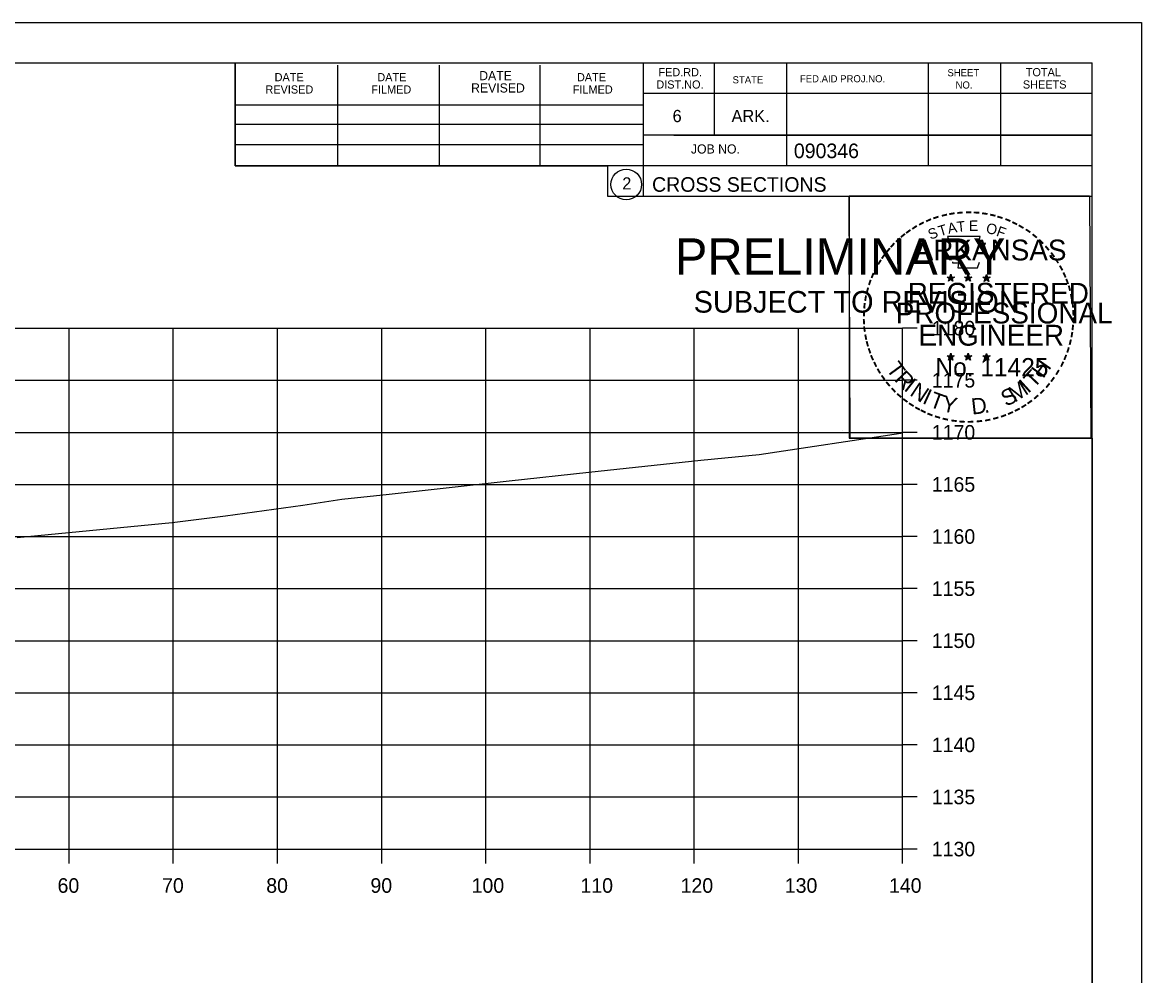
# Model space of a CAD drawing. Extents: x 1368971 to 1374497, y 378717 to 381839.
# Drawn here: x 1369609.3 to 1369716.8, y 380922.1 to 381013.6 of the extents above; entities that cross this region are included whole.
import ezdxf

# ---------------------------------------------------------------- set-up
doc = ezdxf.new("R2010")
doc.units = 0
for name, color, linetype in [('R_Axis', 7, 'Continuous'), ('R_Axis Annot', 7, 'Continuous'), ('R_Border', 7, 'Continuous'), ('R_Border PE', 7, 'Continuous'), ('R_Border Prem', 7, 'Continuous'), ('R_Exist Surface', 7, 'Continuous'), ('R_Grid', 7, 'Continuous'), ('R_No Plot', 7, 'Continuous')]:
    doc.layers.add(name, color=color, linetype=linetype)

msp = doc.modelspace()

# ---------------------------------------------------------------- linework, layer by layer
at = {"layer": 'R_Axis'}
for p, q in [((1369693.83, 380934.26), (1369693.83, 380984.26)), ((1369695.23, 380984.26), (1369693.83, 380984.26)), ((1369695.23, 380979.26), (1369693.83, 380979.26)), ((1369695.23, 380974.26), (1369693.83, 380974.26)), ((1369695.23, 380969.26), (1369693.83, 380969.26)), ((1369695.23, 380964.26), (1369693.83, 380964.26)), ((1369695.23, 380959.26), (1369693.83, 380959.26)), ((1369695.23, 380954.26), (1369693.83, 380954.26)), ((1369695.23, 380949.26), (1369693.83, 380949.26)), ((1369695.23, 380944.26), (1369693.83, 380944.26)), ((1369695.23, 380939.26), (1369693.83, 380939.26)), ((1369413.83, 380934.26), (1369693.83, 380934.26)), ((1369613.83, 380932.86), (1369613.83, 380934.26)), ((1369623.83, 380932.86), (1369623.83, 380934.26)), ((1369633.83, 380932.86), (1369633.83, 380934.26)), ((1369643.83, 380932.86), (1369643.83, 380934.26)), ((1369653.83, 380932.86), (1369653.83, 380934.26)), ((1369663.83, 380932.86), (1369663.83, 380934.26)), ((1369673.83, 380932.86), (1369673.83, 380934.26)), ((1369683.83, 380932.86), (1369683.83, 380934.26)), ((1369693.83, 380932.86), (1369693.83, 380934.26)), ((1369695.23, 380934.26), (1369693.83, 380934.26))]:
    msp.add_line(p, q, dxfattribs=at)
at = {"layer": 'R_Border'}
for p, q in [((1369395.83, 381009.72), (1369712.01, 381009.72)), ((1369629.75, 380999.84), (1369629.75, 381009.72)), ((1369668.91, 381009.72), (1369668.91, 380996.92)), ((1369675.75, 381009.72), (1369675.75, 381002.78)), ((1369682.69, 381009.72), (1369682.69, 380999.84)), ((1369696.27, 381009.72), (1369696.27, 380999.84)), ((1369703.21, 381009.72), (1369703.21, 380999.84)), ((1369712.01, 380804.26), (1369712.01, 381009.72)), ((1369639.61, 380999.84), (1369639.61, 381009.52)), ((1369649.37, 380999.84), (1369649.37, 381009.52)), ((1369659.05, 380999.84), (1369659.05, 381009.52)), ((1369712.01, 381006.78), (1369668.91, 381006.78)), ((1369712.01, 381006.8), (1369712.01, 381006.8)), ((1369629.75, 381005.7), (1369668.91, 381005.7)), ((1369629.75, 381003.84), (1369668.91, 381003.84)), ((1369712.01, 381002.78), (1369668.91, 381002.78)), ((1369671.87, 381002.78), (1369712.01, 381002.78)), ((1369629.75, 380999.84), (1369629.75, 381001.9)), ((1369629.75, 381001.9), (1369668.91, 381001.9)), ((1369712.01, 380999.84), (1369629.75, 380999.84)), ((1369668.91, 380996.92), (1369712.01, 380996.92))]:
    msp.add_line(p, q, dxfattribs=at)
msp.add_circle((1369667.3, 380998.05), 1.47, dxfattribs=at)
at = {"layer": 'R_Border PE'}
for p, q in [((1369698.1, 380989.17), (1369698.45, 380989.06)), ((1369698.1, 380989.17), (1369698.35, 380989.13)), ((1369698.1, 380989.17), (1369698.34, 380989.05)), ((1369698.45, 380989.43), (1369698.41, 380989.17)), ((1369698.45, 380989.06), (1369698.45, 380989.43)), ((1369698.45, 380989.43), (1369698.5, 380989.18)), ((1369698.8, 380989.17), (1369698.45, 380989.06)), ((1369698.8, 380989.17), (1369698.51, 380989.12)), ((1369698.8, 380989.17), (1369698.59, 380989.07)), ((1369699.77, 380989.17), (1369700.12, 380989.06)), ((1369699.77, 380989.17), (1369700.02, 380989.13)), ((1369699.77, 380989.17), (1369700.01, 380989.05)), ((1369700.12, 380989.43), (1369700.08, 380989.17)), ((1369700.12, 380989.06), (1369700.12, 380989.43)), ((1369700.12, 380989.43), (1369700.17, 380989.18)), ((1369700.47, 380989.17), (1369700.12, 380989.06)), ((1369700.47, 380989.17), (1369700.18, 380989.12)), ((1369700.47, 380989.17), (1369700.26, 380989.07)), ((1369701.53, 380989.16), (1369701.88, 380989.05)), ((1369701.53, 380989.16), (1369701.79, 380989.11)), ((1369701.53, 380989.16), (1369701.77, 380989.04)), ((1369701.88, 380989.41), (1369701.84, 380989.16)), ((1369701.88, 380989.05), (1369701.88, 380989.41)), ((1369701.88, 380989.41), (1369701.93, 380989.16)), ((1369702.23, 380989.16), (1369701.88, 380989.05)), ((1369702.23, 380989.16), (1369701.94, 380989.11)), ((1369702.23, 380989.16), (1369702.03, 380989.06)), ((1369698.23, 380988.76), (1369698.45, 380989.06)), ((1369698.23, 380988.76), (1369698.36, 380989.01)), ((1369698.23, 380988.76), (1369698.45, 380988.98)), ((1369698.66, 380988.76), (1369698.45, 380989.06)), ((1369698.66, 380988.76), (1369698.45, 380988.98)), ((1369698.66, 380988.76), (1369698.52, 380989.05)), ((1369699.9, 380988.76), (1369700.12, 380989.06)), ((1369699.9, 380988.76), (1369700.03, 380989.01)), ((1369699.9, 380988.76), (1369700.12, 380988.98)), ((1369700.33, 380988.76), (1369700.12, 380989.06)), ((1369700.33, 380988.76), (1369700.12, 380988.98)), ((1369700.33, 380988.76), (1369700.19, 380989.05)), ((1369701.67, 380988.75), (1369701.88, 380989.05)), ((1369701.67, 380988.75), (1369701.79, 380989)), ((1369701.67, 380988.75), (1369701.88, 380988.97)), ((1369702.1, 380988.75), (1369701.88, 380989.05)), ((1369702.1, 380988.75), (1369701.88, 380988.97)), ((1369702.1, 380988.75), (1369701.96, 380989.04)), ((1369698.44, 380981.85), (1369698.4, 380981.6)), ((1369698.44, 380981.49), (1369698.44, 380981.85)), ((1369698.44, 380981.85), (1369698.49, 380981.6)), ((1369700.11, 380981.85), (1369700.07, 380981.6)), ((1369700.11, 380981.49), (1369700.11, 380981.85)), ((1369700.11, 380981.85), (1369700.16, 380981.6)), ((1369701.88, 380981.84), (1369701.84, 380981.59)), ((1369701.88, 380981.48), (1369701.88, 380981.84)), ((1369701.88, 380981.84), (1369701.93, 380981.59)), ((1369698.1, 380981.6), (1369698.44, 380981.49)), ((1369698.1, 380981.6), (1369698.35, 380981.55)), ((1369698.1, 380981.6), (1369698.33, 380981.48)), ((1369698.23, 380981.19), (1369698.44, 380981.49)), ((1369698.23, 380981.19), (1369698.35, 380981.43)), ((1369698.23, 380981.19), (1369698.44, 380981.41)), ((1369698.79, 380981.6), (1369698.44, 380981.49)), ((1369698.66, 380981.19), (1369698.44, 380981.49)), ((1369698.66, 380981.19), (1369698.44, 380981.4)), ((1369698.79, 380981.6), (1369698.51, 380981.55)), ((1369698.66, 380981.19), (1369698.52, 380981.48)), ((1369698.79, 380981.6), (1369698.59, 380981.5)), ((1369699.76, 380981.6), (1369700.11, 380981.49)), ((1369699.76, 380981.6), (1369700.02, 380981.55)), ((1369699.76, 380981.6), (1369700, 380981.48)), ((1369699.9, 380981.19), (1369700.11, 380981.49)), ((1369699.9, 380981.19), (1369700.02, 380981.43)), ((1369699.9, 380981.19), (1369700.11, 380981.41)), ((1369700.46, 380981.6), (1369700.11, 380981.49)), ((1369700.33, 380981.19), (1369700.11, 380981.49)), ((1369700.33, 380981.19), (1369700.11, 380981.4)), ((1369700.46, 380981.6), (1369700.17, 380981.55)), ((1369700.33, 380981.19), (1369700.19, 380981.48)), ((1369700.46, 380981.6), (1369700.26, 380981.5)), ((1369701.53, 380981.59), (1369701.88, 380981.48)), ((1369701.53, 380981.59), (1369701.78, 380981.54)), ((1369701.53, 380981.59), (1369701.77, 380981.47)), ((1369701.66, 380981.18), (1369701.88, 380981.48)), ((1369701.66, 380981.18), (1369701.79, 380981.42)), ((1369701.66, 380981.18), (1369701.88, 380981.4)), ((1369702.23, 380981.59), (1369701.88, 380981.48)), ((1369702.09, 380981.18), (1369701.88, 380981.48)), ((1369702.09, 380981.18), (1369701.88, 380981.39)), ((1369702.23, 380981.59), (1369701.94, 380981.54)), ((1369702.09, 380981.18), (1369701.96, 380981.47)), ((1369702.23, 380981.59), (1369702.02, 380981.49))]:
    msp.add_line(p, q, dxfattribs=at)
for points in [[(1369698.14, 380993.05), (1369698.41, 380992.22)], [(1369701.65, 380992.13), (1369701.79, 380992.41), (1369701.11, 380992.39), (1369701.26, 380993.05), (1369698.14, 380993.05)], [(1369698.63, 380990.63), (1369698.63, 380990.54), (1369699.2, 380990.52), (1369699.14, 380990.05), (1369701.01, 380990.05), (1369701.21, 380990.58)], [(1369698.45, 380989.43), (1369698.66, 380988.76), (1369698.1, 380989.17), (1369698.8, 380989.17), (1369698.23, 380988.76), (1369698.45, 380989.43)], [(1369700.12, 380989.43), (1369700.33, 380988.76), (1369699.77, 380989.17), (1369700.47, 380989.17), (1369699.9, 380988.76), (1369700.12, 380989.43)], [(1369701.88, 380989.41), (1369702.1, 380988.75), (1369701.53, 380989.16), (1369702.23, 380989.16), (1369701.67, 380988.75), (1369701.88, 380989.41)], [(1369698.44, 380981.85), (1369698.66, 380981.19), (1369698.1, 380981.6), (1369698.79, 380981.6), (1369698.23, 380981.19), (1369698.44, 380981.85)], [(1369700.11, 380981.85), (1369700.33, 380981.19), (1369699.76, 380981.6), (1369700.46, 380981.6), (1369699.9, 380981.19), (1369700.11, 380981.85)], [(1369701.88, 380981.84), (1369702.09, 380981.18), (1369701.53, 380981.59), (1369702.23, 380981.59), (1369701.66, 380981.18), (1369701.88, 380981.84)]]:
    msp.add_lwpolyline(points, dxfattribs=at)
for centre, radius in [((1369698.45, 380989.06), 0.172), ((1369698.45, 380989.06), 0.145), ((1369698.45, 380989.06), 0.116), ((1369698.45, 380989.06), 0.0991), ((1369698.45, 380989.06), 0.0747), ((1369700.12, 380989.06), 0.172), ((1369700.12, 380989.06), 0.145), ((1369700.12, 380989.06), 0.116), ((1369700.12, 380989.06), 0.0991), ((1369700.12, 380989.06), 0.0747), ((1369701.88, 380989.05), 0.172), ((1369701.88, 380989.05), 0.145), ((1369701.88, 380989.05), 0.116), ((1369701.88, 380989.05), 0.0991), ((1369698.45, 380989.06), 0.0495), ((1369698.45, 380989.06), 0.0296), ((1369700.12, 380989.06), 0.0495), ((1369700.12, 380989.06), 0.0296), ((1369701.88, 380989.05), 0.0747), ((1369701.88, 380989.05), 0.0495), ((1369701.88, 380989.05), 0.0296), ((1369698.44, 380981.49), 0.172), ((1369698.44, 380981.49), 0.145), ((1369700.11, 380981.49), 0.172), ((1369700.11, 380981.49), 0.145), ((1369701.88, 380981.48), 0.172), ((1369701.88, 380981.48), 0.145), ((1369698.44, 380981.49), 0.116), ((1369698.44, 380981.49), 0.0991), ((1369698.44, 380981.49), 0.0747), ((1369698.44, 380981.49), 0.0495), ((1369698.44, 380981.49), 0.0296), ((1369700.11, 380981.49), 0.116), ((1369700.11, 380981.49), 0.0991), ((1369700.11, 380981.49), 0.0747), ((1369700.11, 380981.49), 0.0495), ((1369700.11, 380981.49), 0.0296), ((1369701.88, 380981.48), 0.116), ((1369701.88, 380981.48), 0.0991), ((1369701.88, 380981.48), 0.0747), ((1369701.88, 380981.48), 0.0495), ((1369701.88, 380981.48), 0.0296)]:
    msp.add_circle(centre, radius, dxfattribs=at)
at = {"layer": 'R_Exist Surface'}
msp.add_lwpolyline([(1369608.84, 380964.18), (1369623.73, 380965.59), (1369628.85, 380966.23), (1369636.25, 380967.27), (1369640, 380967.85), (1369644.55, 380968.34), (1369656.06, 380969.61), (1369663.7, 380970.45), (1369674.46, 380971.59), (1369680.05, 380972.12), (1369693.66, 380974.19), (1369693.83, 380974.21)], dxfattribs=at)
at = {"layer": 'R_Grid'}
for p, q in [((1369413.83, 380984.26), (1369693.83, 380984.26)), ((1369613.83, 380934.26), (1369613.83, 380984.26)), ((1369623.83, 380934.26), (1369623.83, 380984.26)), ((1369633.83, 380934.26), (1369633.83, 380984.26)), ((1369643.83, 380934.26), (1369643.83, 380984.26)), ((1369653.83, 380934.26), (1369653.83, 380984.26)), ((1369663.83, 380934.26), (1369663.83, 380984.26)), ((1369673.83, 380934.26), (1369673.83, 380984.26)), ((1369683.83, 380934.26), (1369683.83, 380984.26)), ((1369693.83, 380934.26), (1369693.83, 380984.26)), ((1369413.83, 380979.26), (1369693.83, 380979.26)), ((1369413.83, 380974.26), (1369693.83, 380974.26)), ((1369413.83, 380969.26), (1369693.83, 380969.26)), ((1369413.83, 380964.26), (1369693.83, 380964.26)), ((1369413.83, 380959.26), (1369693.83, 380959.26)), ((1369413.83, 380954.26), (1369693.83, 380954.26)), ((1369413.83, 380949.26), (1369693.83, 380949.26)), ((1369413.83, 380944.26), (1369693.83, 380944.26)), ((1369413.83, 380939.26), (1369693.83, 380939.26)), ((1369413.83, 380934.26), (1369693.83, 380934.26))]:
    msp.add_line(p, q, dxfattribs=at)
at = {"layer": 'R_No Plot'}
for p, q in [((1369383.43, 381013.61), (1369716.77, 381013.61)), ((1369688.05, 380974.46), (1369688.05, 380974.46))]:
    msp.add_line(p, q, dxfattribs=at)
for points in [[(1369383.43, 381013.61), (1369716.77, 381013.61), (1369716.77, 380800.27), (1369383.43, 380800.27)], [(1369629.75, 381009.72), (1369629.75, 380999.84), (1369665.49, 380999.84), (1369665.49, 380996.92), (1369688.69, 380996.92), (1369688.69, 380973.7), (1369712.01, 380973.7), (1369712.01, 380804.26), (1369395.83, 380804.26), (1369395.83, 381009.72)], [(1369688.69, 380996.95), (1369711.78, 380996.95), (1369711.9, 380973.7), (1369688.8, 380973.7)]]:
    msp.add_lwpolyline(points, close=True, dxfattribs=at)

# ---------------------------------------------------------------- texts
at = {"layer": 'R_Axis Annot'}
for s, p in [('1180', (1369696.63, 380983.56)), ('1175', (1369696.63, 380978.56)), ('1170', (1369696.63, 380973.56)), ('1165', (1369696.63, 380968.56)), ('1160', (1369696.63, 380963.56)), ('1155', (1369696.63, 380958.56)), ('1150', (1369696.63, 380953.56)), ('1145', (1369696.63, 380948.56)), ('1140', (1369696.63, 380943.56)), ('1135', (1369696.63, 380938.56)), ('1130', (1369696.63, 380933.56)), ('60', (1369612.72, 380930.06)), ('70', (1369622.75, 380930.06)), ('80', (1369632.75, 380930.06)), ('90', (1369642.75, 380930.06)), ('100', (1369652.46, 380930.06)), ('110', (1369662.91, 380930.06)), ('120', (1369672.52, 380930.06)), ('130', (1369682.52, 380930.06)), ('140', (1369692.52, 380930.06))]:
    msp.add_text(s, height=1.4, dxfattribs=at).set_placement(p)
at = {"layer": 'R_Border'}
for s, height, p in [('DATE', 0.782, (1369633.55, 381007.96)), ('DATE', 0.782, (1369643.41, 381007.96)), ('DATE', 0.879, (1369653.19, 381008.06)), ('DATE', 0.782, (1369662.57, 381007.96)), ('FED.RD.', 0.782, (1369670.39, 381008.44)), ('FED.AID PROJ.NO.', 0.684, (1369683.97, 381007.86)), ('SHEET', 0.684, (1369698.13, 381008.44)), ('TOTAL', 0.782, (1369705.65, 381008.44)), ('REVISED', 0.782, (1369632.67, 381006.78)), ('FILMED', 0.782, (1369642.83, 381006.78)), ('REVISED', 0.879, (1369652.41, 381006.88)), ('FILMED', 0.782, (1369662.17, 381006.78)), ('DIST.NO.', 0.782, (1369670.19, 381007.26)), ('STATE', 0.684, (1369677.51, 381007.76)), ('NO.', 0.684, (1369698.91, 381007.26)), ('SHEETS', 0.782, (1369705.37, 381007.26)), ('6', 1.17, (1369671.75, 381004.04)), ('ARK.', 1.172, (1369677.41, 381004.04)), ('JOB NO.', 0.879, (1369673.51, 381001.02)), ('2', 1.17, (1369666.92, 380997.57)), ('CROSS SECTIONS', 1.4, (1369669.78, 380997.35))]:
    msp.add_text(s, height=height, dxfattribs=at).set_placement(p)
msp.add_text('090346', height=1.4, rotation=360, dxfattribs=at).set_placement((1369683.39, 381000.58))
at = {"layer": 'R_Border PE'}
for s, height, rotation, p in [('-', 1.6, 28.7918, (1369695.62, 380993.59)), ('-', 1.6, 24.3072, (1369696.25, 380993.91)), ('-', 1.6, 19.1761, (1369696.89, 380994.18)), ('-', 1.6, 13.6301, (1369697.64, 380994.42)), ('-', 1.6, 10.2193, (1369698.32, 380994.58)), ('T', 1, 6.0228, (1369699.08, 380993.48)), ('-', 1.6, 5.8968, (1369699.05, 380994.69)), ('-', 1.6, 0.1862, (1369699.82, 380994.76)), ('E', 1, 0.8323, (1369700.19, 380993.59)), ('-', 1.6, 357.743, (1369700.54, 380994.75)), ('-', 1.6, 352.1617, (1369701.28, 380994.69)), ('-', 1.6, 347.2049, (1369702, 380994.58)), ('-', 1.6, 342.3362, (1369702.64, 380994.42)), ('-', 1.6, 337.8551, (1369703.37, 380994.2)), ('-', 1.6, 334.1211, (1369704, 380993.93)), ('-', 1.6, 36.2317, (1369694.45, 380992.83)), ('-', 1.6, 34.0636, (1369695.02, 380993.22)), ('S', 1, 21.594, (1369696.5, 380992.73)), ('T', 1, 16.4036, (1369697.41, 380993.06)), ('A', 1, 11.2132, (1369698.24, 380993.31)), ('O', 1, 350.4515, (1369701.79, 380993.38)), ('F', 1, 340.0707, (1369702.75, 380993.15)), ('-', 1.6, 329.6409, (1369704.58, 380993.65)), ('-', 1.6, 325.8627, (1369705.23, 380993.29)), ('-', 1.6, 48.423, (1369693.09, 380991.55)), ('-', 1.6, 42.9622, (1369693.54, 380992.03)), ('-', 1.6, 38.9507, (1369693.97, 380992.45)), ('-', 1.6, 320.5297, (1369705.84, 380992.86)), ('-', 1.6, 315.5786, (1369706.44, 380992.37)), ('-', 1.6, 54.2325, (1369692.27, 380990.5)), ('-', 1.6, 50.6142, (1369692.69, 380991.07)), ('-', 1.6, 309.8797, (1369707, 380991.82)), ('-', 1.6, 306.6522, (1369707.53, 380991.22)), ('-', 1.6, 62.8713, (1369691.64, 380989.36)), ('-', 1.6, 58.0706, (1369691.95, 380989.97)), ('-', 1.4, 303.6753, (1369708.02, 380990.65)), ('-', 1.6, 299.6684, (1369708.33, 380990.04)), ('-', 1.6, 67.7743, (1369691.38, 380988.75)), ('-', 1.6, 294.6628, (1369708.66, 380989.43)), ('-', 1.6, 75.461, (1369690.96, 380987.4)), ('-', 1.6, 72.3945, (1369691.16, 380988.12)), ('-', 1.6, 290.5728, (1369708.92, 380988.86)), ('-', 1.6, 285.1233, (1369709.15, 380988.28)), ('-', 1.6, 81.2013, (1369690.83, 380986.69)), ('-', 1.6, 280.5493, (1369709.35, 380987.53)), ('-', 1.6, 89.0622, (1369690.73, 380985.3)), ('-', 1.6, 85.1863, (1369690.75, 380986)), ('-', 1.6, 276.5962, (1369709.51, 380986.77)), ('-', 1.6, 274.3301, (1369709.57, 380986.04)), ('-', 1.6, 94.1959, (1369690.76, 380984.57)), ('-', 1.6, 269.9407, (1369709.61, 380985.41)), ('-', 1.6, 98.9479, (1369690.83, 380983.91)), ('-', 1.6, 260.9953, (1369709.52, 380984.09)), ('-', 1.6, 263.5172, (1369709.59, 380984.75)), ('-', 1.6, 101.7149, (1369690.97, 380983.17)), ('-', 1.6, 105.4578, (1369691.13, 380982.58)), ('-', 1.6, 255.7626, (1369709.41, 380983.41)), ('-', 1.6, 109.0874, (1369691.35, 380981.95)), ('-', 1.6, 114.0643, (1369691.6, 380981.35)), ('-', 1.6, 247.8887, (1369709, 380982.02)), ('-', 1.6, 252.8681, (1369709.22, 380982.69)), ('-', 1.6, 115.7288, (1369691.91, 380980.73)), ('T', 1.54, 306.0406, (1369692.2, 380980.33)), ('H', 1.54, 54.6088, (1369707.32, 380979.36)), ('-', 1.6, 244.6197, (1369708.74, 380981.39)), ('-', 1.6, 120.4471, (1369692.26, 380980.15)), ('-', 1.6, 125.8934, (1369692.67, 380979.59)), ('R', 1.54, 314.005, (1369692.97, 380979.28)), ('T', 1.54, 46.6444, (1369706.43, 380978.42)), ('-', 1.6, 233.8452, (1369707.94, 380979.99)), ('-', 1.6, 239.0712, (1369708.35, 380980.64)), ('-', 1.6, 130.7181, (1369693.13, 380979.03)), ('-', 1.6, 134.2238, (1369693.64, 380978.49)), ('I', 1.54, 321.9694, (1369693.87, 380978.35)), ('N', 1.54, 326.5002, (1369694.43, 380977.87)), ('I', 1.54, 335.3603, (1369695.64, 380977.09)), ('S', 1.54, 26.9312, (1369703.75, 380976.69)), ('M', 1.54, 32.6563, (1369704.59, 380977.09)), ('I', 1.54, 42.1136, (1369705.87, 380977.94)), ('-', 1.6, 225.7653, (1369707.03, 380978.86)), ('-', 1.6, 231.2538, (1369707.51, 380979.42)), ('-', 1.6, 138.9338, (1369694.17, 380978.03)), ('-', 1.6, 144.6463, (1369694.73, 380977.62)), ('T', 1.54, 339.8912, (1369696.3, 380976.76)), ('Y', 1.54, 347.8556, (1369697.52, 380976.32)), ('D', 1.54, 6.3969, (1369700.5, 380975.96)), ('-', 1.6, 215.7363, (1369705.96, 380977.88)), ('-', 1.6, 221.0851, (1369706.51, 380978.35)), ('-', 1.6, 148.0898, (1369695.29, 380977.25)), ('-', 1.6, 151.5704, (1369695.87, 380976.92)), ('-', 1.6, 154.6002, (1369696.39, 380976.68)), ('.', 1.54, 13.7642, (1369701.7, 380976.08)), ('-', 1.6, 204.2516, (1369704.25, 380976.82)), ('-', 1.6, 207.3568, (1369704.87, 380977.14)), ('-', 1.6, 212.2491, (1369705.43, 380977.49)), ('-', 1.6, 158.5612, (1369697.01, 380976.42)), ('-', 1.6, 162.7983, (1369697.7, 380976.21)), ('-', 1.6, 167.5555, (1369698.41, 380976.05)), ('-', 1.6, 173.1155, (1369699.19, 380975.94)), ('-', 1.6, 176.5183, (1369699.93, 380975.88)), ('-', 1.6, 181.5918, (1369700.68, 380975.9)), ('-', 1.6, 185.8167, (1369701.49, 380975.98)), ('-', 1.6, 191.2858, (1369702.22, 380976.11)), ('-', 1.6, 195.4743, (1369702.95, 380976.31)), ('-', 1.6, 200.7184, (1369703.63, 380976.55))]:
    msp.add_text(s, height=height, rotation=rotation, dxfattribs=at).set_placement(p)
for s, height, p in [('ARKANSAS', 2, (1369694.99, 380990.76)), ('REGISTERED', 2, (1369694.32, 380986.61)), ('DWB', 0.01, (1369698.44, 380989.06)), ('DWB', 0.01, (1369700.11, 380989.06)), ('DWB', 0.01, (1369701.87, 380989.04)), ('PROFESSIONAL', 2, (1369693.17, 380984.71)), ('ENGINEER', 2, (1369695.35, 380982.58)), ('No. 11425', 1.757, (1369696.98, 380979.63)), ('DWB', 0.01, (1369698.43, 380981.48)), ('DWB', 0.01, (1369700.1, 380981.48)), ('DWB', 0.01, (1369701.87, 380981.47))]:
    msp.add_text(s, height=height, dxfattribs=at).set_placement(p)
at = {"layer": 'R_Border Prem'}
for s, height, p in [('PRELIMINARY', 3.5, (1369671.97, 380989.38)), ('DWB', 0.01, (1369672.71, 380991.23)), ('SUBJECT TO REVISION', 2.0751, (1369673.77, 380985.75))]:
    msp.add_text(s, height=height, dxfattribs=at).set_placement(p)

doc.saveas('drawing.dxf')
